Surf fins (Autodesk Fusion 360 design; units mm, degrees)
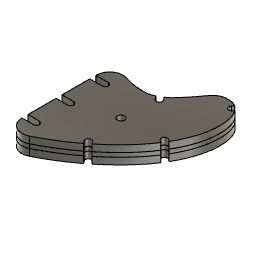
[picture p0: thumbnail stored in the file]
sketch "Boceto1" plane through (0, 0, 0) normal (0, 0, 1) x axis (1, 0, 0)
  curve K1 (127.2511, 53.079) -> (191.2428, 94.641)
  line L1 (130.3426, 48.5562) -> (127.2511, 53.079)
  line L2 (119.4565, 48.5344) -> (122.9129, 43.4777)
  curve K2 (72.7541, 50.0769) -> (119.4565, 48.5344)
  line L3 (47.4121, 30.1743) -> (47.4121, 30.8035)
  line L4 (66.2597, 30.1743) -> (47.4121, 30.1743)
  line L5 (47.4121, 21.1743) -> (66.2597, 21.1743)
  line L6 (47.4121, -20.5) -> (47.4121, 21.1743)
  line L7 (65, -20.5) -> (47.4121, -20.5)
  line L8 (47.4121, -29.5) -> (65, -29.5)
  line L9 (47.4121, -71.5722) -> (47.4121, -29.5)
  line L10 (64.577, -71.5628) -> (47.4121, -71.5722)
  line L11 (47.4121, -80.5628) -> (64.5794, -80.5628)
  line L12 (47.4121, -80.7692) -> (47.4121, -80.5628)
  curve K3 (126.6383, -67.4093) -> (76.7065, -98.4784)
  line L13 (123.6708, -63.6257) -> (126.6383, -67.4093)
  line L14 (133.7147, -61.8494) -> (130.7521, -58.0719)
  curve K4 (183.479, -8.4471) -> (133.7147, -61.8494)
  line L15 (179.6876, -5.4702) -> (183.479, -8.4471)
  line L16 (188.2607, -0.7601) -> (185.2449, 1.6078)
  curve K5 (197.7932, 88.4574) -> (188.2607, -0.7601)
  line L17 (195.8244, 86.1861) -> (197.7932, 88.4574)
  line L18 (191.2428, 94.641) -> (189.0237, 92.0809)
  arc A1 centre (126.653, 45.9801) radius 4.5 clockwise from (130.3426, 48.5562) to (122.9129, 43.4777)
  arc A2 centre (67.4121, 30.8035) radius 20 clockwise from (47.4121, 30.8035) to (72.7541, 50.0769)
  arc A3 centre (66.2597, 25.6743) radius 4.5 clockwise from (66.2597, 30.1743) to (66.2597, 21.1743)
  arc A4 centre (65, -25) radius 4.5 clockwise from (65, -20.5) to (65, -29.5)
  arc A5 centre (64.5794, -76.0628) radius 4.5 clockwise from (64.577, -71.5628) to (64.5794, -80.5628)
  arc A6 centre (67.4121, -80.7692) radius 20 clockwise from (76.7065, -98.4784) to (47.4121, -80.7692)
  arc A7 centre (127.179, -60.8075) radius 4.5 clockwise from (123.6708, -63.6257) to (130.7521, -58.0719)
  arc A8 centre (182.414, -1.8902) radius 4.5 clockwise from (179.6876, -5.4702) to (185.2449, 1.6078)
  arc A9 centre (192.4088, 89.1159) radius 4.5 clockwise from (195.8244, 86.1861) to (189.0237, 92.0809)
extrude "Extruir1" new body sketch "Boceto1" along normal blind 10
sketch "Boceto2" plane through (0, 0, 10) normal (0, 0, 1) x axis (1, 0, 0)
  curve K1 (-137.1272, 94.641) -> (-73.1355, 53.079)
  line L1 (-134.9081, 92.0809) -> (-137.1272, 94.641)
  line L2 (-143.6776, 88.4574) -> (-141.7088, 86.1861)
  curve K2 (-134.1451, -0.7601) -> (-143.6776, 88.4574)
  line L3 (-131.1293, 1.6078) -> (-134.1451, -0.7601)
  line L4 (-129.3634, -8.4471) -> (-125.572, -5.4702)
  curve K3 (-79.5991, -61.8494) -> (-129.3634, -8.4471)
  line L5 (-76.6365, -58.0719) -> (-79.5991, -61.8494)
  line L6 (-72.5227, -67.4093) -> (-69.5552, -63.6257)
  curve K4 (-22.5909, -98.4784) -> (-72.5227, -67.4093)
  line L7 (6.7035, -80.5628) -> (6.7035, -80.7692)
  line L8 (-10.4638, -80.5628) -> (6.7035, -80.5628)
  line L9 (6.7035, -71.5722) -> (-10.4614, -71.5628)
  line L10 (6.7035, -29.5) -> (6.7035, -71.5722)
  line L11 (-10.8844, -29.5) -> (6.7035, -29.5)
  line L12 (6.7035, -20.5) -> (-10.8844, -20.5)
  line L13 (6.7035, 21.1743) -> (6.7035, -20.5)
  line L14 (-12.1441, 21.1743) -> (6.7035, 21.1743)
  line L15 (6.7035, 30.1743) -> (-12.1441, 30.1743)
  line L16 (6.7035, 30.8035) -> (6.7035, 30.1743)
  curve K5 (-65.3409, 48.5344) -> (-18.6385, 50.0769)
  line L17 (-68.7973, 43.4777) -> (-65.3409, 48.5344)
  line L18 (-73.1355, 53.079) -> (-76.227, 48.5562)
  line L19 (-22.3619, 12.3432) -> (-22.3619, 33.4794)
  line L20 (-8.2965, 12.3131) -> (-22.3619, 12.3432)
  line L21 (-8.2965, -8.7795) -> (-8.2965, 12.3131)
  line L22 (-22.3619, -8.7494) -> (-8.2965, -8.7795)
  line L23 (-22.3619, -42.175) -> (-22.3619, -8.7494)
  line L24 (-8.2958, -42.1793) -> (-22.3619, -42.175)
  line L25 (-8.2958, -63.3591) -> (-8.2958, -42.1793)
  line L26 (-22.3619, -63.3547) -> (-8.2958, -63.3591)
  line L27 (-22.3619, -81.6582) -> (-22.3619, -63.3547)
  curve K6 (-22.3619, 33.4794) -> (-22.3619, -81.6582)
  arc A1 centre (-138.2933, 89.1159) radius 4.5 clockwise from (-134.9081, 92.0809) to (-141.7088, 86.1861)
  arc A2 centre (-128.2984, -1.8902) radius 4.5 clockwise from (-131.1293, 1.6078) to (-125.572, -5.4702)
  arc A3 centre (-73.0634, -60.8075) radius 4.5 clockwise from (-76.6365, -58.0719) to (-69.5552, -63.6257)
  arc A4 centre (-13.2965, -80.7692) radius 20 clockwise from (6.7035, -80.7692) to (-22.5909, -98.4784)
  arc A5 centre (-10.4638, -76.0628) radius 4.5 clockwise from (-10.4638, -80.5628) to (-10.4614, -71.5628)
  arc A6 centre (-10.8844, -25) radius 4.5 clockwise from (-10.8844, -29.5) to (-10.8844, -20.5)
  arc A7 centre (-12.1441, 25.6743) radius 4.5 clockwise from (-12.1441, 21.1743) to (-12.1441, 30.1743)
  arc A8 centre (-13.2965, 30.8035) radius 20 clockwise from (-18.6385, 50.0769) to (6.7035, 30.8035)
  arc A9 centre (-72.5374, 45.9801) radius 4.5 clockwise from (-68.7973, 43.4777) to (-76.227, 48.5562)
extrude "Extruir2" new body sketch "Boceto2" along normal blind 6
sketch "Boceto3" plane through (0, 0, 0) normal (0, 0, 1) x axis (1, 0, 0)
  curve K1 (-191.2428, 298.2243) -> (-127.2511, 256.6623)
  line L1 (-189.0237, 295.6642) -> (-191.2428, 298.2243)
  line L2 (-197.7932, 292.0407) -> (-195.8244, 289.7694)
  curve K2 (-188.2607, 202.8232) -> (-197.7932, 292.0407)
  line L3 (-185.2449, 205.1911) -> (-188.2607, 202.8232)
  line L4 (-183.479, 195.1362) -> (-179.6876, 198.1131)
  curve K3 (-133.7147, 141.7339) -> (-183.479, 195.1362)
  line L5 (-130.7521, 145.5114) -> (-133.7147, 141.7339)
  line L6 (-126.6383, 136.174) -> (-123.6708, 139.9576)
  curve K4 (-76.7065, 105.1049) -> (-126.6383, 136.174)
  line L7 (-47.4121, 123.0205) -> (-47.4121, 122.8141)
  line L8 (-64.5794, 123.0205) -> (-47.4121, 123.0205)
  line L9 (-47.4121, 132.0111) -> (-64.577, 132.0205)
  line L10 (-47.4121, 174.0833) -> (-47.4121, 132.0111)
  line L11 (-65, 174.0833) -> (-47.4121, 174.0833)
  line L12 (-47.4121, 183.0833) -> (-65, 183.0833)
  line L13 (-47.4121, 224.7576) -> (-47.4121, 183.0833)
  line L14 (-66.2597, 224.7576) -> (-47.4121, 224.7576)
  line L15 (-47.4121, 233.7576) -> (-66.2597, 233.7576)
  line L16 (-47.4121, 234.3868) -> (-47.4121, 233.7576)
  curve K5 (-119.4565, 252.1177) -> (-72.7541, 253.6602)
  line L17 (-122.9129, 247.061) -> (-119.4565, 252.1177)
  line L18 (-127.2511, 256.6623) -> (-130.3426, 252.1395)
  circle C1 centre (-121.6589, 197.1742) radius 5.5
  arc A1 centre (-192.4088, 292.6992) radius 4.5 clockwise from (-189.0237, 295.6642) to (-195.8244, 289.7694)
  arc A2 centre (-182.414, 201.6931) radius 4.5 clockwise from (-185.2449, 205.1911) to (-179.6876, 198.1131)
  arc A3 centre (-127.179, 142.7759) radius 4.5 clockwise from (-130.7521, 145.5114) to (-123.6708, 139.9576)
  arc A4 centre (-67.4121, 122.8141) radius 20 clockwise from (-47.4121, 122.8141) to (-76.7065, 105.1049)
  arc A5 centre (-64.5794, 127.5205) radius 4.5 clockwise from (-64.5794, 123.0205) to (-64.577, 132.0205)
  arc A6 centre (-65, 178.5833) radius 4.5 clockwise from (-65, 174.0833) to (-65, 183.0833)
  arc A7 centre (-66.2597, 229.2576) radius 4.5 clockwise from (-66.2597, 224.7576) to (-66.2597, 233.7576)
  arc A8 centre (-67.4121, 234.3868) radius 20 clockwise from (-72.7541, 253.6602) to (-47.4121, 234.3868)
  arc A9 centre (-126.653, 249.5634) radius 4.5 clockwise from (-122.9129, 247.061) to (-130.3426, 252.1395)
extrude "Extruir3" new body sketch "Boceto3" along normal blind 10
move "Desplazar1"
move "Desplazar2"
move "Desplazar3"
